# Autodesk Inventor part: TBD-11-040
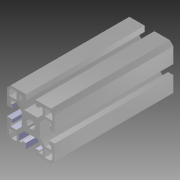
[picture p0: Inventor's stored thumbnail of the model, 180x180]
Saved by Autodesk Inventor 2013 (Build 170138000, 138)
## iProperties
Created: 2004-10
Material: Aluminium - 6061
Document SubType Name: Modeling
Designer: Autodesk, Inc.
Manufacturer: Standard
Standards Organization: Custom
Description: 40 SERIES, 40X40, HEAVY PROFILE
Stock Number: 11-040
Catalog Web Link: http://www.parker.com/ead/cm1.asp?cmid=809
Vendor: PARKER IPS
Part Number: TBD-11-040
Mass: 179.948 g
Surface Area: 483.565 cm^2
Volume: 66.4013 cm^3
Density: 2.71 g/cm^3
CAGE: 1LJX3
Dept. ID: Product Design
Description #2: ---
Finish #1: ---
Finish #2: ---
Material ID: ---
Project Number: ---
Length: 100.000 mm
Author: Autodesk, Inc.
Revision Number: --
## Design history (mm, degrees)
derived "40 Series Profiles.ipt"
body "Solid1"
tag "TaggingFeature2"
feature "Solid1::40 Series Profiles.ipt" dims "ScaleForDerivedMember" = 10
other parameters: "Length" = 100
